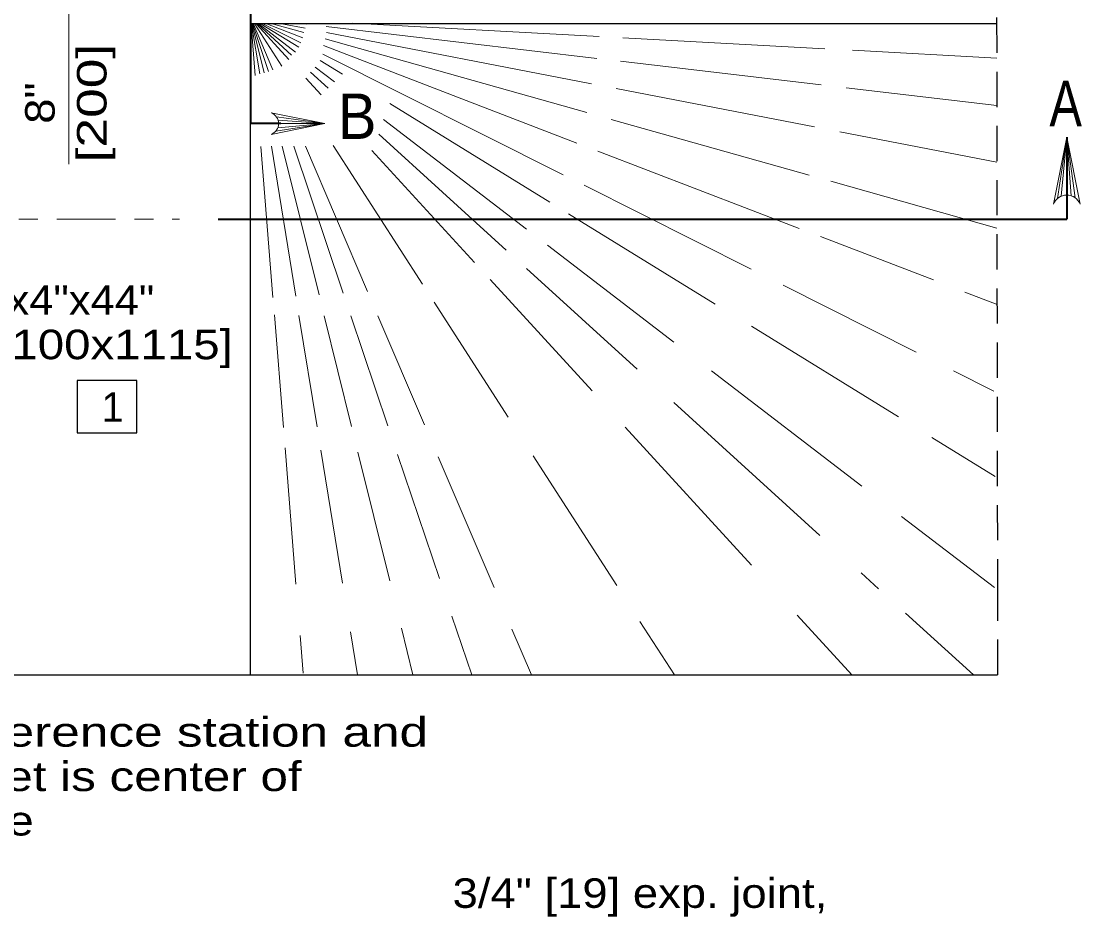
# Model space of a CAD drawing. Extents: x 1083.1 to 1123, y 697.4 to 741.4.
# Drawn here: x 1097.03 to 1102.63, y 729.09 to 733.82 of the extents above; entities that cross this region are included whole.
import ezdxf
from ezdxf.enums import TextEntityAlignment as Align

# ---------------------------------------------------------------- set-up
doc = ezdxf.new("R2010")
doc.units = 0
doc.header["$LTSCALE"] = 0.062
doc.linetypes.add('DOT_DASHED', pattern=[7.7, 5, -1.2, 0.3, -1.2])
doc.linetypes.add('MEDIUM_DASHED', pattern=[4.5, 3, -1.5])
doc.layers.add('1', color=7, linetype='Continuous', lineweight=13)

msp = doc.modelspace()

# ---------------------------------------------------------------- linework, layer by layer
at = {"layer": '1'}
for p, q in [((1097.28358, 734.28208), (1097.28358, 733.06067)), ((1098.2465, 733.79842), (1098.26817, 733.52875)), ((1098.24942, 733.7985), (1098.29208, 733.53625)), ((1098.25242, 733.7985), (1098.31583, 733.542)), ((1098.25558, 733.7985), (1098.33925, 733.54975)), ((1098.25875, 733.79858), (1098.36125, 733.55875)), ((1098.26642, 733.79867), (1098.40875, 733.57792)), ((1098.27583, 733.79875), (1098.44533, 733.61342)), ((1098.28225, 733.79883), (1098.46092, 733.63642)), ((1098.28933, 733.79892), (1098.48217, 733.65117)), ((1098.30025, 733.799), (1098.49808, 733.67708)), ((1098.31283, 733.79917), (1098.51, 733.70008)), ((1098.33367, 733.79933), (1098.52075, 733.7275)), ((1098.365, 733.79967), (1098.52475, 733.75458)), ((1098.4175, 733.80025), (1098.5325, 733.77792)), ((1098.5205, 733.80125), (1098.53775, 733.79925)), ((1098.6425, 733.78692), (1100.07342, 733.61825)), ((1098.78342, 733.80467), (1100.08467, 733.73425)), ((1098.6375, 733.72283), (1100.01933, 733.33308)), ((1098.64567, 733.756), (1100.04558, 733.48492)), ((1100.21083, 733.72742), (1101.27717, 733.66975)), ((1098.62883, 733.686), (1099.96775, 733.17183)), ((1101.424, 733.66175), (1102.18475, 733.62058)), ((1098.612, 733.60692), (1098.72917, 733.53475)), ((1098.626, 733.64183), (1099.89558, 733.00392)), ((1100.19717, 733.60367), (1101.2585, 733.47867)), ((1098.56117, 733.54542), (1098.653, 733.46192)), ((1098.586, 733.57167), (1098.68692, 733.49433)), ((1098.53608, 733.51425), (1098.61617, 733.42675)), ((1100.17525, 733.45975), (1101.22342, 733.25675)), ((1101.39025, 733.46308), (1102.18517, 733.36942)), ((1098.97933, 733.38058), (1099.82425, 732.86)), ((1098.37742, 733.23458), (1098.63683, 733.27425)), ((1098.38042, 733.31008), (1098.63683, 733.27425)), ((1098.38717, 733.25117), (1098.63683, 733.27425)), ((1098.38908, 733.29233), (1098.63683, 733.27425)), ((1098.39175, 733.27425), (1098.63683, 733.27425)), ((1098.94692, 733.29525), (1099.70175, 732.71692)), ((1100.14875, 733.29658), (1101.19508, 733.0015)), ((1098.9215, 733.21792), (1099.59408, 732.6065)), ((1101.35575, 733.23108), (1102.1855, 733.07042)), ((1098.29825, 733.15417), (1098.36225, 732.35617)), ((1098.35425, 733.15458), (1098.48308, 732.36325)), ((1098.41167, 733.15458), (1098.6055, 732.37042)), ((1098.47233, 733.15458), (1098.73358, 732.37867)), ((1098.53417, 733.15458), (1098.86233, 732.38708)), ((1098.6795, 733.15817), (1099.15167, 732.42617)), ((1102.5055, 732.87867), (1102.55508, 733.203)), ((1102.52625, 732.891), (1102.55508, 733.203)), ((1102.55508, 732.89667), (1102.55508, 733.203)), ((1102.57775, 732.89333), (1102.55508, 733.203)), ((1102.59992, 732.8825), (1102.55508, 733.203)), ((1098.88508, 733.13283), (1099.42692, 732.54067)), ((1100.078, 733.1295), (1101.14167, 732.721)), ((1100.00533, 732.94883), (1100.88758, 732.50558)), ((1101.30825, 732.96958), (1102.186, 732.72208)), ((1099.92392, 732.79858), (1100.6985, 732.32133)), ((1101.25458, 732.67767), (1101.85058, 732.44883)), ((1099.81208, 732.63242), (1100.48, 732.12083)), ((1099.70133, 732.50908), (1100.28592, 731.97742)), ((1099.50933, 732.45058), (1100.04758, 731.86233)), ((1101.05725, 732.42033), (1101.75992, 732.06733)), ((1102.01692, 732.38492), (1102.18658, 732.31975)), ((1099.21317, 732.33083), (1099.60467, 731.72383)), ((1098.36967, 732.264), (1098.41742, 731.669)), ((1098.49958, 732.26158), (1098.5955, 731.67217)), ((1098.633, 732.25917), (1098.77733, 731.67542)), ((1098.77392, 732.259), (1098.96925, 731.67883)), ((1098.91708, 732.259), (1099.16333, 731.68325)), ((1100.88917, 732.20383), (1101.66583, 731.72533)), ((1100.67775, 731.96942), (1101.47325, 731.36)), ((1101.95683, 731.96833), (1102.16933, 731.86158)), ((1100.47875, 731.80208), (1101.25083, 731.09983)), ((1100.22292, 731.67075), (1100.89008, 730.94167)), ((1101.84267, 731.61642), (1102.17625, 731.41092)), ((1098.426, 731.56183), (1098.48392, 730.84117)), ((1098.61542, 731.55), (1098.72992, 730.84675)), ((1098.81108, 731.53875), (1098.97908, 730.85933)), ((1099.0205, 731.52675), (1099.24108, 730.8715)), ((1099.23542, 731.51467), (1099.53083, 730.82392)), ((1099.73625, 731.51983), (1100.17858, 730.83408)), ((1101.68217, 731.2), (1102.17258, 730.82425)), ((1101.46892, 730.9015), (1101.56108, 730.81767)), ((1101.70375, 730.68925), (1102.06308, 730.36267)), ((1099.30767, 730.67383), (1099.41242, 730.36267)), ((1100.30058, 730.645), (1100.48267, 730.36267)), ((1101.13092, 730.67833), (1101.41967, 730.36267)), ((1098.7715, 730.591), (1098.80867, 730.36267)), ((1099.04067, 730.61008), (1099.10183, 730.36267)), ((1099.62442, 730.60492), (1099.728, 730.36267)), ((1098.5055, 730.57158), (1098.5215, 730.37242))]:
    msp.add_line(p, q, dxfattribs=at)
at = {"layer": '1', "lineweight": 35}
for p, q in [((1098.24367, 734.28208), (1098.24367, 733.27425)), ((1098.40358, 733.27425), (1098.24367, 733.27425)), ((1102.55508, 733.203), (1102.55508, 732.77033)), ((1098.07358, 732.77033), (1102.55508, 732.77033))]:
    msp.add_line(p, q, dxfattribs=at)
at = {"layer": '1', "lineweight": 25}
for p, q in [((1098.24367, 733.80242), (1102.18458, 733.80242)), ((1098.24367, 730.36267), (1098.24367, 733.27425)), ((1086.34158, 730.36267), (1102.18933, 730.36267))]:
    msp.add_line(p, q, dxfattribs=at)
at = {"layer": '1', "linetype": 'DOT_DASHED'}
msp.add_line((1092.34058, 732.77033), (1097.86783, 732.77033), dxfattribs=at)
at = {"layer": '1', "linetype": 'MEDIUM_DASHED', "lineweight": 25}
msp.add_lwpolyline([(1102.1845, 733.83392), (1102.18867, 730.835), (1102.18933, 730.36267)], dxfattribs=at)
at = {"layer": '1'}
for points in [[(1098.35358, 733.21758), (1098.63683, 733.27425), (1098.35358, 733.33083)], [(1102.48425, 732.849), (1102.55508, 733.203), (1102.62583, 732.849)]]:
    msp.add_lwpolyline(points, dxfattribs=at)
at = {"layer": '1', "lineweight": 25}
msp.add_lwpolyline([(1097.32892, 731.91708), (1097.32892, 731.64175), (1097.64325, 731.64175), (1097.64325, 731.91708)], close=True, dxfattribs=at)
at = {"layer": '1'}
for centre, radius, start, end in [((1098.33073, 733.27428), 0.06112, 292.08605, 67.91218), ((1102.55513, 732.82039), 0.0764, 22.08782, 157.91395)]:
    msp.add_arc(centre, radius, start, end, dxfattribs=at)

# ---------------------------------------------------------------- texts
for s, width, p in [('[200]', 1.35, (1097.48325, 733.38258)), ('8"', 1.15, (1097.20925, 733.38258))]:
    msp.add_text(s, height=0.156, rotation=90, dxfattribs=dict(at, width=width)).set_placement(p, align=Align.CENTER)
for s, height, width, p in [('A', 0.24, 0.8, (1102.46358, 733.26067)), ('B', 0.24, 0.95, (1098.70567, 733.19317)), ('4 1/2"x4"x44"', 0.156, 1.1, (1096.3685, 732.2645)), ('[115x100x1115]', 0.156, 1.2, (1096.3685, 732.02983)), ('Reference station and ', 0.156, 1.3, (1096.52825, 729.98392)), ('offset is center of', 0.156, 1.25, (1096.52825, 729.74925)), ('grate', 0.156, 1.2, (1096.52825, 729.51458)), ('3/4" [19] exp. joint,', 0.156, 1.15, (1099.311, 729.13242))]:
    msp.add_text(s, height=height, dxfattribs=dict(at, width=width)).set_placement(p)
msp.add_text('1', height=0.156, dxfattribs=at).set_placement((1097.4575, 731.69967))

doc.saveas('drawing.dxf')
